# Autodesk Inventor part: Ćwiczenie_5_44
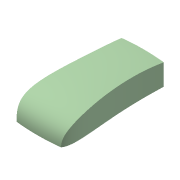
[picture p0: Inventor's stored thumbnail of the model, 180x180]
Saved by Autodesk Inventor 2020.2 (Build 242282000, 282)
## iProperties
Created: 2006-08
Part Number: Ćwiczenie_5_44
Document SubType Name: Modeling
Designer: F.Stasiak
Density: 1 g/cm^3
Material: Ogólny
Appearance: Zielony pastelowy
Manager: www.cadconsulting.pl
Company: Fabian Stasiak CAD Consulting
Author: F.Stasiak
Subject: Zbiór ćwiczeń. Autodesk Inventor 2020. Kurs podstawowy
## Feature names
1. Wyciągnięcie proste1 [Extrusion]
## Parameters: d3 = 0, d4 = 0, d8 = 0
